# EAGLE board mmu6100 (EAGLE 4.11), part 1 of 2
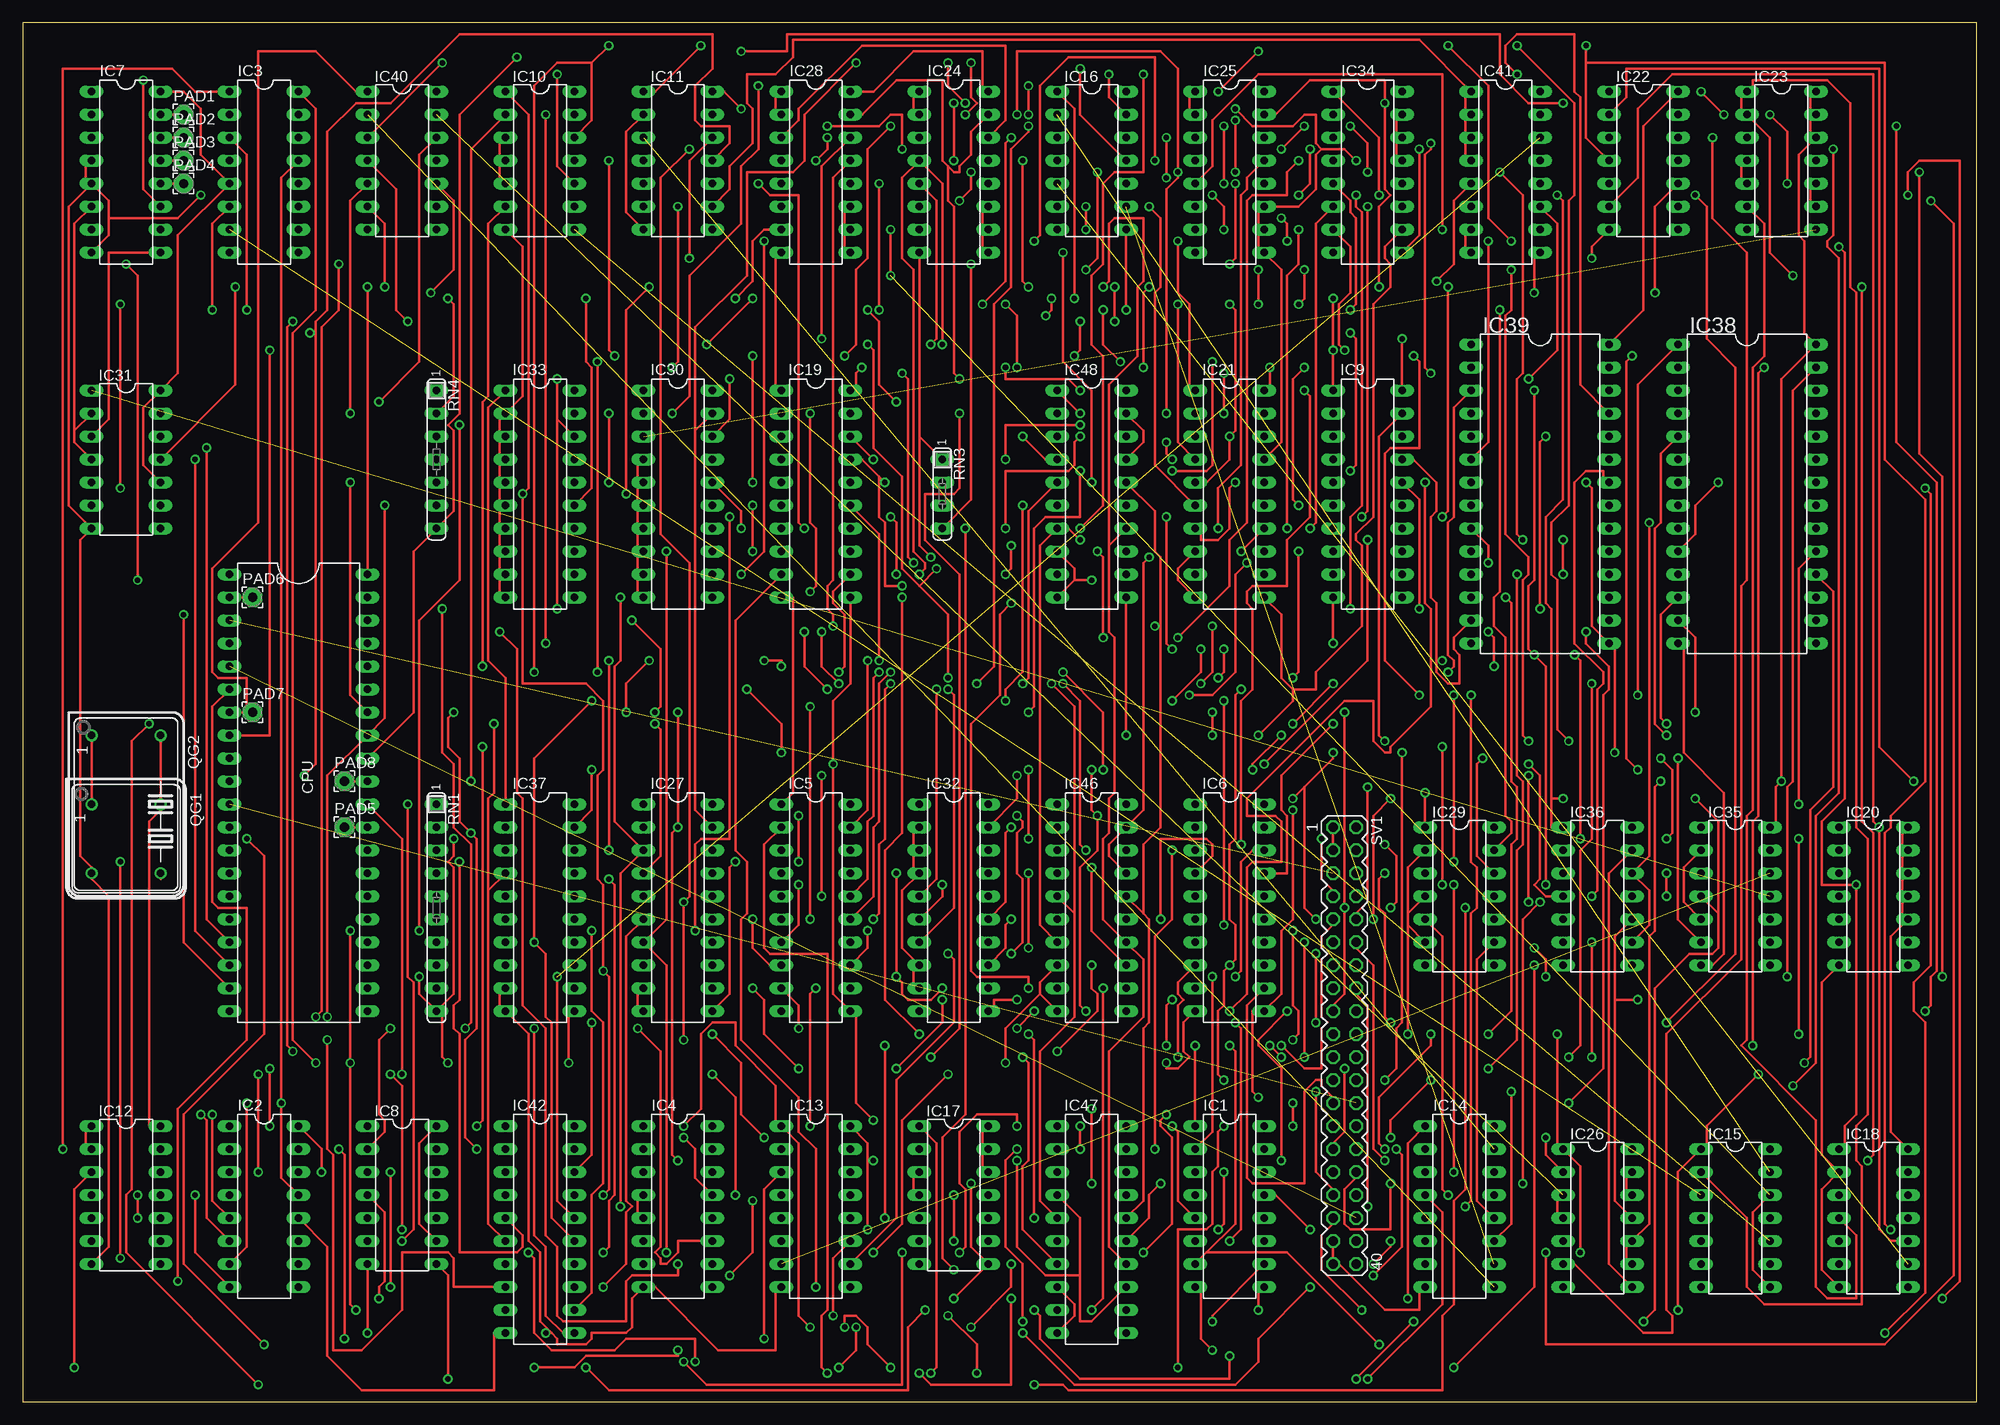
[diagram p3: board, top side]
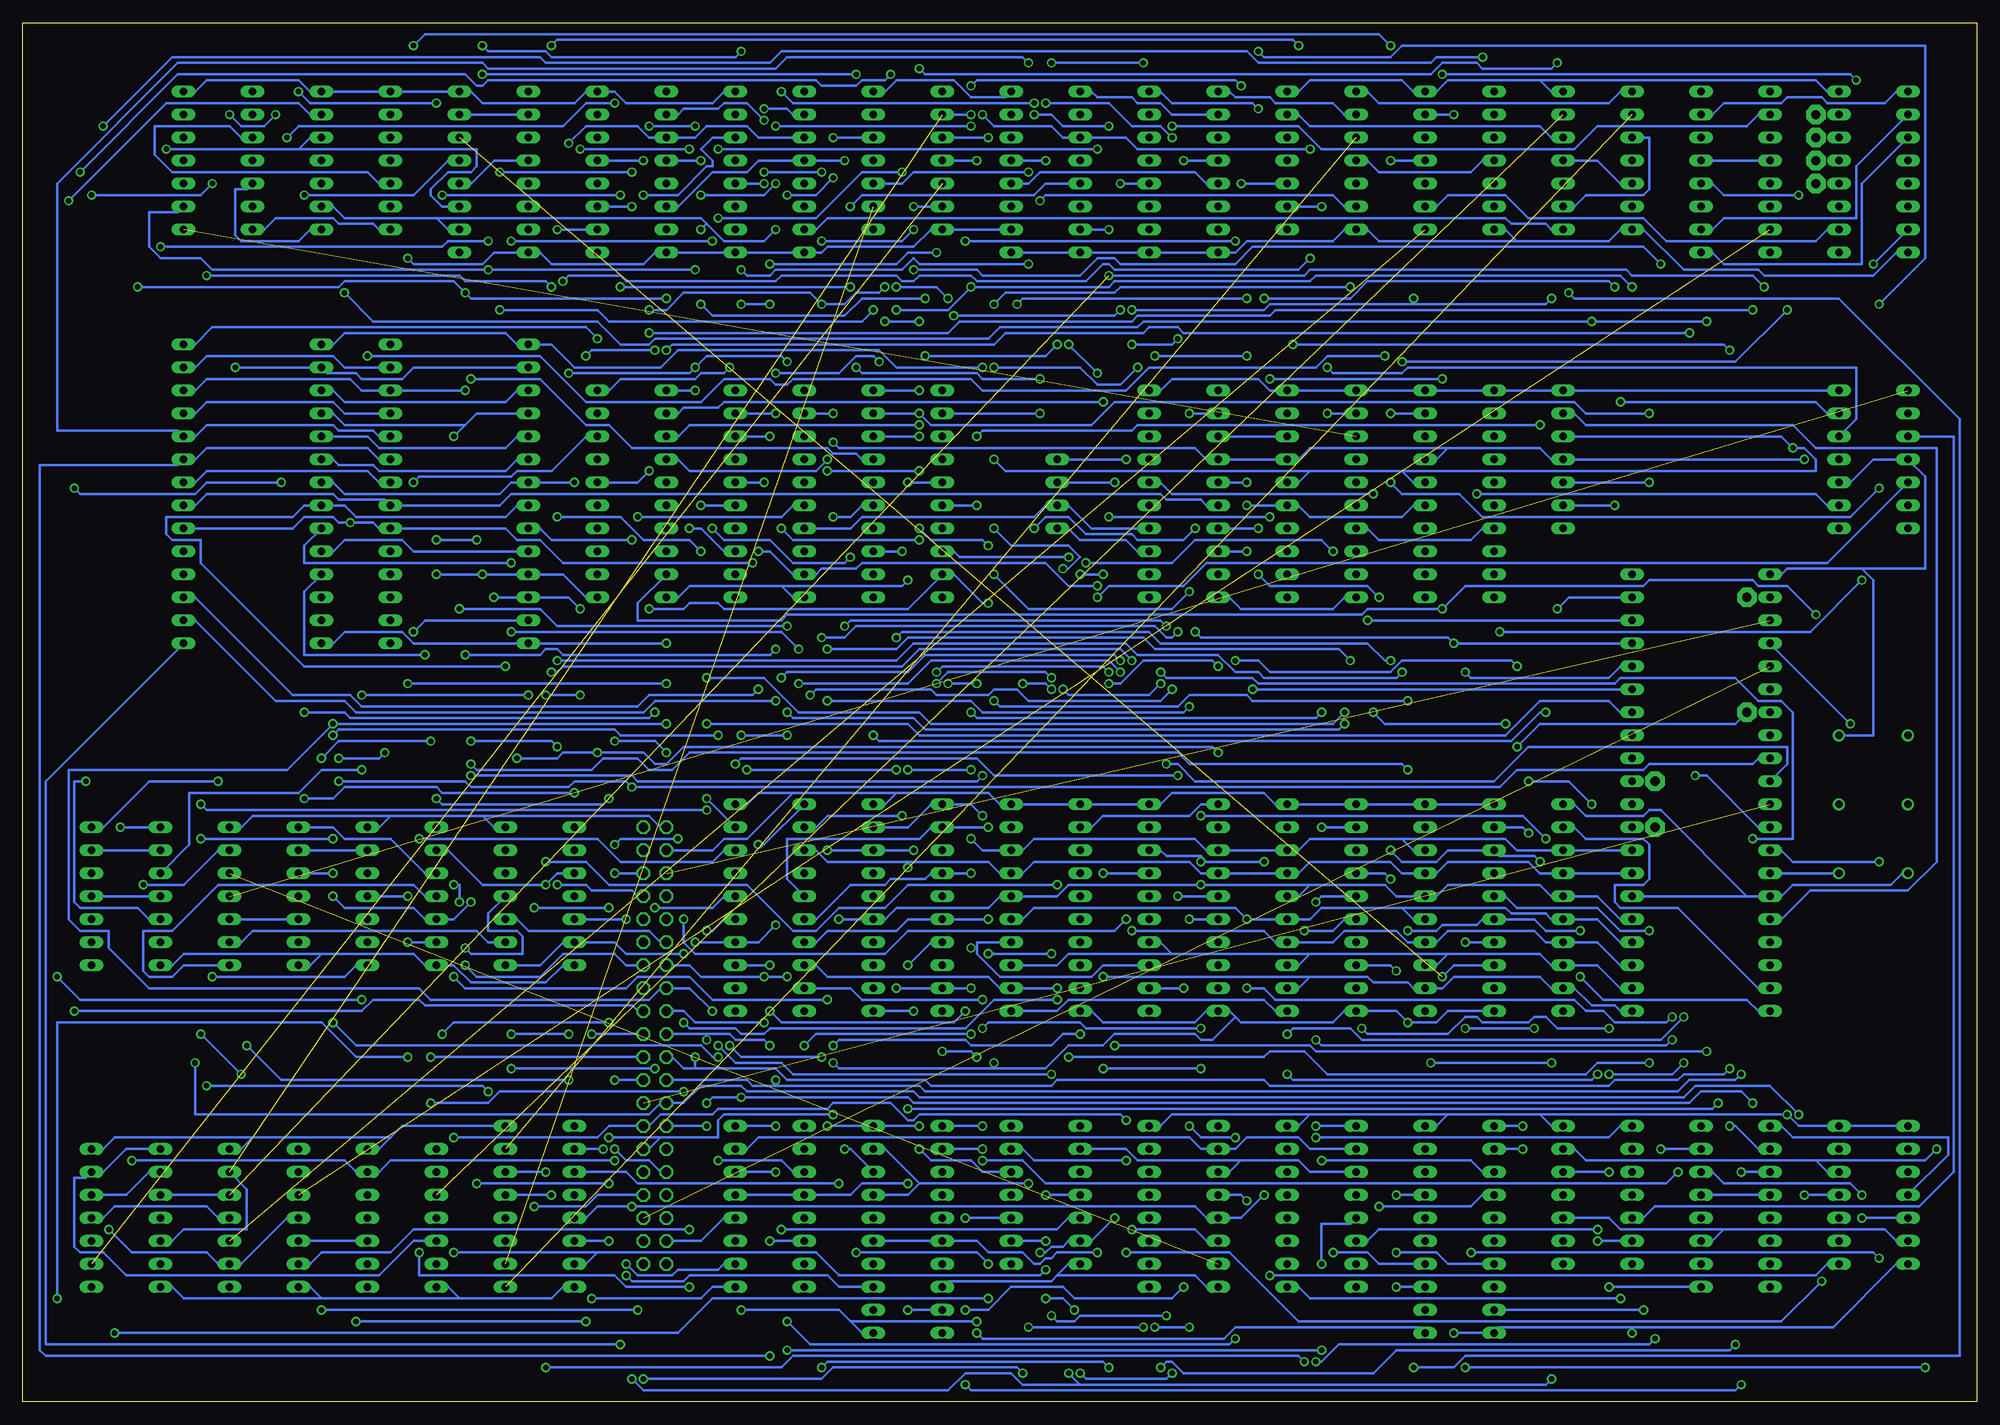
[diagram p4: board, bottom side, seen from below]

Size 215.9 x 152.4 mm. Coordinates in mm from the lower left corner, seen from the top.
Outline: 0,0 215.9,0 215.9,152.4 0,152.4 0,0
Copper layers (1*16): Top 0.035mm / dielectric 1.5mm / Bottom 0.035mm
Design rules "10mils": minimum track width 10mil, minimum drill 24mil, track to track 10mil, track to pad 10mil, pad to pad 10mil, via to via 10mil, smd to smd 10mil, copper to edge 40mil, drill to drill 10mil, minimum pad ring 10mil, minimum via ring 8mil, stop-mask expansion 0mil, vias tented up to drill 0mil, thermal gap 10mil

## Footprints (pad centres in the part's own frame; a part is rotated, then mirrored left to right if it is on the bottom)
DIL40 = drill 0.813 long: 1 -24.13,-7.62; 2 -21.59,-7.62; 3 -19.05,-7.62; 4 -16.51,-7.62; 5 -13.97,-7.62; 6 -11.43,-7.62; 7 -8.89,-7.62; 8 -6.35,-7.62; 9 -3.81,-7.62; 10 -1.27,-7.62; 11 1.27,-7.62; 12 3.81,-7.62; 13 6.35,-7.62; 14 8.89,-7.62; 15 11.43,-7.62; 16 13.97,-7.62; 17 16.51,-7.62; 18 19.05,-7.62; 19 21.59,-7.62; 20 24.13,-7.62; 21 24.13,7.62; 22 21.59,7.62; 23 19.05,7.62; 24 16.51,7.62; 25 13.97,7.62; 26 11.43,7.62; 27 8.89,7.62; 28 6.35,7.62; 29 3.81,7.62; 30 1.27,7.62; 31 -1.27,7.62; 32 -3.81,7.62; 33 -6.35,7.62; 34 -8.89,7.62; 35 -11.43,7.62; 36 -13.97,7.62; 37 -16.51,7.62; 38 -19.05,7.62; 39 -21.59,7.62; 40 -24.13,7.62
DIL16 = drill 0.813 long: 1 -8.89,-3.81; 2 -6.35,-3.81; 3 -3.81,-3.81; 4 -1.27,-3.81; 5 1.27,-3.81; 6 3.81,-3.81; 7 6.35,-3.81; 8 8.89,-3.81; 9 8.89,3.81; 10 6.35,3.81; 11 3.81,3.81; 12 1.27,3.81; 13 -1.27,3.81; 14 -3.81,3.81; 15 -6.35,3.81; 16 -8.89,3.81
DIL20 = drill 0.813 long: 1 -11.43,-3.81; 2 -8.89,-3.81; 3 -6.35,-3.81; 4 -3.81,-3.81; 5 -1.27,-3.81; 6 1.27,-3.81; 7 3.81,-3.81; 8 6.35,-3.81; 9 8.89,-3.81; 10 11.43,-3.81; 11 11.43,3.81; 12 8.89,3.81; 13 6.35,3.81; 14 3.81,3.81; 15 1.27,3.81; 16 -1.27,3.81; 17 -3.81,3.81; 18 -6.35,3.81; 19 -8.89,3.81; 20 -11.43,3.81
DIL14 = drill 0.813 long: 1 -7.62,-3.81; 2 -5.08,-3.81; 3 -2.54,-3.81; 4 0,-3.81; 5 2.54,-3.81; 6 5.08,-3.81; 7 7.62,-3.81; 8 7.62,3.81; 9 5.08,3.81; 10 2.54,3.81; 11 0,3.81; 12 -2.54,3.81; 13 -5.08,3.81; 14 -7.62,3.81
DIL28-6 = drill 0.813 long: 1 -16.51,-7.62; 2 -13.97,-7.62; 3 -11.43,-7.62; 4 -8.89,-7.62; 5 -6.35,-7.62; 6 -3.81,-7.62; 7 -1.27,-7.62; 8 1.27,-7.62; 9 3.81,-7.62; 10 6.35,-7.62; 11 8.89,-7.62; 12 11.43,-7.62; 13 13.97,-7.62; 14 16.51,-7.62; 15 16.51,7.62; 16 13.97,7.62; 17 11.43,7.62; 18 8.89,7.62; 19 6.35,7.62; 20 3.81,7.62; 21 1.27,7.62; 22 -1.27,7.62; 23 -3.81,7.62; 24 -6.35,7.62; 25 -8.89,7.62; 26 -11.43,7.62; 27 -13.97,7.62; 28 -16.51,7.62
2,15/1,0 = drill 1.016 pad 2.159 octagon: 1 0,0
DIL08S = drill 0.813 round: 1 -3.81,-3.81; 4 3.81,-3.81; 5 3.81,3.81; 8 -3.81,3.81
DIL14S = drill 0.813 round: 1 -7.62,-3.81; 7 7.62,-3.81; 8 7.62,3.81; 14 -7.62,3.81
SIL10 = drill 0.813 long: 1 -11.43,0; 2 -8.89,0; 3 -6.35,0; 4 -3.81,0; 5 -1.27,0; 6 1.27,0; 7 3.81,0; 8 6.35,0; 9 8.89,0; 10 11.43,0
SIL4 = drill 0.813 long: 1 -3.81,0; 2 -1.27,0; 3 1.27,0; 4 3.81,0
SIL7 = drill 0.813 long: 1 -7.62,0; 2 -5.08,0; 3 -2.54,0; 4 0,0; 5 2.54,0; 6 5.08,0; 7 7.62,0
MA20-2 = drill 1.016 octagon: 1 -24.13,-1.27; 2 -24.13,1.27; 3 -21.59,-1.27; 4 -21.59,1.27; 5 -19.05,-1.27; 6 -19.05,1.27; 7 -16.51,-1.27; 8 -16.51,1.27; 9 -13.97,-1.27; 10 -13.97,1.27; 11 -11.43,-1.27; 12 -11.43,1.27; 13 -8.89,-1.27; 14 -8.89,1.27; 15 -6.35,-1.27; 16 -6.35,1.27; 17 -3.81,-1.27; 18 -3.81,1.27; 19 -1.27,-1.27; 20 -1.27,1.27; 21 1.27,-1.27; 22 1.27,1.27; 23 3.81,-1.27; 24 3.81,1.27; 25 6.35,-1.27; 26 6.35,1.27; 27 8.89,-1.27; 28 8.89,1.27; 29 11.43,-1.27; 30 11.43,1.27; 31 13.97,-1.27; 32 13.97,1.27; 33 16.51,-1.27; 34 16.51,1.27; 35 19.05,-1.27; 36 19.05,1.27; 37 21.59,-1.27; 38 21.59,1.27; 39 24.13,-1.27; 40 24.13,1.27

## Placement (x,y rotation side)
CPU  IM6100  [DIL40]  30.48,67.31 270 top
IC1  74LS75N  [DIL16]  133.35,21.59 270 top
IC2  74LS75N  [DIL16]  26.67,21.59 270 top
IC3  74LS75N  [DIL16]  26.67,135.89 270 top
IC4  74HCT138N  [DIL16]  72.39,21.59 270 top
IC5  74LS373N  [DIL20]  87.63,54.61 270 top
IC6  74LS245N  [DIL20]  133.35,54.61 270 top
IC7  74HCT138N  [DIL16]  11.43,135.89 270 top
IC8  [DIL14]  41.91,22.86 270 top
IC9  74LS245N  [DIL20]  148.59,100.33 270 top
IC10  74HCT00N  [DIL14]  57.15,137.16 270 top
IC11  74LS74N  [DIL14]  72.39,137.16 270 top
IC12  74LS30N  [DIL14]  11.43,22.86 270 top
IC13  74HCT138N  [DIL16]  87.63,21.59 270 top
IC14  74HCT138N  [DIL16]  158.75,21.59 270 top
IC15  74HCT08N  [DIL14]  189.23,20.32 270 top
IC16  74LS32N  [DIL14]  118.11,137.16 270 top
IC17  74LS32N  [DIL14]  102.87,22.86 270 top
IC18  74LS74N  [DIL14]  204.47,20.32 270 top
IC19  74LS373N  [DIL20]  87.63,100.33 270 top
IC20  74LS74N  [DIL14]  204.47,55.88 270 top
IC21  74LS241N  [DIL20]  133.35,100.33 270 top
IC22  [DIL14]  179.07,137.16 270 top
IC23  74HCT00N  [DIL14]  194.31,137.16 270 top
IC24  74LS173N  [DIL16]  102.87,135.89 270 top
IC25  74LS173N  [DIL16]  133.35,135.89 270 top
IC26  74HCT00N  [DIL14]  173.99,20.32 270 top
IC27  74LS245N  [DIL20]  72.39,54.61 270 top
IC28  74LS173N  [DIL16]  87.63,135.89 270 top
IC29  74LS07N  [DIL14]  158.75,55.88 270 top
IC30  74LS245N  [DIL20]  72.39,100.33 270 top
IC31  74LS74N  [DIL14]  11.43,104.14 270 top
IC32  74LS245N  [DIL20]  102.87,54.61 270 top
IC33  74LS245N  [DIL20]  57.15,100.33 270 top
IC34  74LS157N  [DIL16]  148.59,135.89 270 top
IC35  74LS32N  [DIL14]  189.23,55.88 270 top
IC36  74HCT08N  [DIL14]  173.99,55.88 270 top
IC37  74LS245N  [DIL20]  57.15,54.61 270 top
IC38  [DIL28-6]  190.5,100.33 270 top
IC39  [DIL28-6]  167.64,100.33 270 top
IC40  74LS11N  [DIL14]  41.91,137.16 270 top
IC41  74LS151N  [DIL16]  163.83,135.89 270 top
IC42  74LS273N  [DIL20]  57.15,19.05 270 top
IC46  74LS244N  [DIL20]  118.11,54.61 270 top
IC47  74LS244N  [DIL20]  118.11,19.05 270 top
IC48  74LS244N  [DIL20]  118.11,100.33 270 top
PAD1  [2,15/1,0]  17.78,142.24 0 top
PAD2  [2,15/1,0]  17.78,139.7 0 top
PAD3  [2,15/1,0]  17.78,137.16 0 top
PAD4  [2,15/1,0]  17.78,134.62 0 top
PAD5  [2,15/1,0]  35.56,63.5 0 top
PAD6  [2,15/1,0]  25.4,88.9 0 top
PAD7  [2,15/1,0]  25.4,76.2 0 top
PAD8  [2,15/1,0]  35.56,68.58 0 top
QG1  [DIL08S]  11.43,62.23 270 top
QG2  [DIL14S]  11.43,66.04 270 top
RN1  100K  [SIL10]  45.72,54.61 270 top
RN3  100K  [SIL4]  101.6,100.33 270 top
RN4  [SIL7]  45.72,104.14 270 top
SV1  [MA20-2]  146.05,39.37 270 top

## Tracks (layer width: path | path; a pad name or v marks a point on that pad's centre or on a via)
00\  (via drill 0.61)
  Top 0.254: v78.11,13.97 80.64,16.51 v80.64,22.23
  Bottom 0.254: v78.11,13.97 17.78,13.97 16.51,15.24 IC12.8 | v80.64,22.23 81.28,22.86 IC13.4
2X\  (via drill 0.61)
  Top 0.254: v46.99,2.54 46.99,13.97 IC8.8 | v100.33,3.17 100.97,3.81 100.97,28.57 IC17.1 | v148.59,2.54 156.84,10.79 156.84,20.95 IC14.4
  Bottom 0.254: v46.99,2.54 47.62,1.91 99.06,1.91 | 99.06,1.91 v100.33,3.17 | v148.59,2.54 147.32,1.27 113.67,1.27 111.76,3.17 106.68,3.17 105.41,1.91 99.06,1.91
AND\
  Top 0.254: IC7.15 PAD1.1
BFLD0
  Bottom 0.254: IC28.5 85.09,134.62 86.36,135.89 103.5,135.89 104.78,134.62 IC24.12
BFLD1  (via drill 0.61)
  Top 0.254: v87.63,137.16 88.9,138.43 v88.9,139.7 | v102.87,143.51 v102.87,137.16
  Bottom 0.254: v88.9,139.7 90.17,140.97 93.34,140.97 95.89,143.51 v102.87,143.51 | IC28.4 v87.63,137.16 | v102.87,137.16 IC24.13
BFLD2
  Top 0.254: IC28.3 85.72,141.6 85.72,142.88 92.71,149.86 108.58,149.86 108.58,141.6 IC24.14
BFLOAD  (via drill 0.61)
  Top 0.254: v40.01,123.19 40.01,130.18 IC40.6 | v78.74,121.92 80.64,123.83 80.64,128.27 81.92,129.54 IC28.7
  Bottom 0.254: v40.01,123.19 40.64,123.83 67.31,123.83 69.22,121.92 v78.74,121.92
BMUX0  (via drill 0.61)
  Top 0.254: IC47.14 120.02,17.14 120.02,38.73 123.83,42.55 123.83,48.9 IC46.14 119.38,53.34 119.38,62.23 120.02,62.87 120.02,66.67 120.65,67.31 120.65,84.45 120.02,85.09 120.02,94.61 | 120.02,94.61 IC48.14 | v94.61,120.65 v94.61,134.62 | v113.03,120.02 113.67,120.65 v113.67,121.92 | v119.38,123.19 120.02,123.83 120.02,130.18 120.65,130.81 123.83,130.81 123.83,123.83 123.19,123.19 123.19,115.57 120.02,112.39 120.02,94.61
  Bottom 0.254: v94.61,120.65 95.25,120.02 v113.03,120.02 | v113.67,121.92 114.94,123.19 v119.38,123.19 | v94.61,134.62 IC28.12
BMUX1  (via drill 0.61)
  Top 0.254: 123.83,53.98 124.46,53.34 124.46,41.91 123.83,41.27 123.83,22.23 IC47.16 | 123.83,53.98 IC46.16 | 125.73,85.72 125.73,63.5 123.83,61.59 123.83,53.98 | 125.73,85.72 125.73,93.34 125.09,93.98 125.09,98.42 IC48.16 | v89.53,85.72 89.53,87 88.9,87.63 88.9,90.17 89.53,90.81 89.53,135.25 IC28.13 | 125.73,85.72 v125.09,85.72
  Bottom 0.254: v89.53,85.72 90.17,86.36 124.46,86.36 v125.09,85.72
BMUX2  (via drill 0.61)
  Top 0.254: v88.27,117.47 88.27,136.53 IC28.14 | v93.34,116.84 93.98,116.2 93.98,105.41 97.16,102.23 97.16,92.08 99.06,90.17 | 99.06,90.17 102.23,87 v102.23,80.01 | v114.94,79.38 116.84,77.47 116.84,61.59 v117.47,60.96 | v125.09,27.94 125.09,51.44 127,53.34 v127,60.96 | v116.84,106.68 116.2,106.05 116.2,103.5 115.57,102.87 108.58,102.87 v108.58,96.52 | 99.06,90.17 v100.97,92.08
  Bottom 0.254: v88.27,117.47 88.9,116.84 v93.34,116.84 | v102.23,80.01 102.87,80.64 113.67,80.64 v114.94,79.38 | v117.47,60.96 IC46.18 v127,60.96 | v125.09,27.94 124.46,27.94 IC47.18 | v108.58,96.52 106.68,94.61 100.33,94.61 99.06,93.34 100.33,92.08 v100.97,92.08 | v116.84,106.68 IC48.18
C0\  (via drill 0.61)
  Top 0.254: CPU.32 43.18,76.2 43.18,93.98 RN4.7 47.62,98.42 47.62,107.31 46.99,107.95 48.26,109.22 48.26,142.24 v54.61,148.59 | v210.19,43.18 210.82,43.81 210.82,46.99 211.46,47.62 211.46,101.6 207.01,106.05 v207.01,140.97
  Bottom 0.254: v210.19,43.18 178.44,43.18 177.16,44.45 172.09,44.45 171.45,43.81 148.59,43.81 147.96,43.18 SV1.18 | v207.01,140.97 199.39,148.59 158.75,148.59 158.12,147.96 133.35,147.96 132.08,149.22 80.64,149.22 79.38,147.96 60.33,147.96 59.69,148.59 v54.61,148.59
C1\  (via drill 0.61)
  Top 0.254: v40.01,99.06 40.01,75.56 CPU.33 33.66,69.22 v33.66,42.55 | 153.03,52.7 153.03,53.98 | 153.03,53.98 IC29.4 | IC29.6 153.03,52.7 | 153.03,53.98 153.03,59.05 IC29.2 | 153.03,52.7 v153.03,40.64 | v80.64,45.72 81.92,44.45 81.92,40.64 v85.72,36.83 | v96.52,36.83 101.6,41.91 v101.6,44.45 | v142.88,41.91 v142.88,49.53
  Bottom 0.254: v40.01,99.06 RN4.6 | IC29.8 158.75,48.26 156.21,50.8 IC29.6 150.5,50.8 149.22,49.53 v142.88,49.53 | v153.03,40.64 SV1.20 | v33.66,42.55 34.29,41.91 40.01,41.91 41.27,43.18 43.18,43.18 44.45,44.45 77.47,44.45 78.74,45.72 v80.64,45.72 | v85.72,36.83 v96.52,36.83 | v101.6,44.45 108.58,44.45 111.76,41.27 133.35,41.27 133.99,40.64 136.53,40.64 137.16,41.27 142.24,41.27 v142.88,41.91
C2\  (via drill 0.61)
  Top 0.254: v36.2,101.6 36.2,78.11 CPU.34 | v170.81,38.1 172.09,39.37 172.09,60.96 173.35,62.23 v173.35,79.38 | v140.34,74.93 v144.78,79.38
  Bottom 0.254: v36.2,101.6 RN4.5 | v144.78,79.38 v173.35,79.38 | v140.34,74.93 118.11,74.93 116.84,73.66 52.07,73.66 48.26,77.47 40.64,77.47 39.37,76.2 CPU.34 | v170.81,38.1 SV1.22
CAF\  (1 unrouted)
CDF\  (via drill 0.61)
  Top 0.254: v104.78,24.13 104.78,17.14 IC17.8 v102.87,11.43 | v45.09,122.56 47.62,125.09 47.62,132.72 IC40.10 | v62.23,3.81 64.77,1.27 97.79,1.27 97.79,8.26 v99.69,10.16
  Bottom 0.254: v104.78,24.13 116.84,24.13 | 116.84,24.13 118.11,22.86 IC47.17 | 116.84,24.13 120.65,27.94 IC47.19 | v45.09,122.56 44.45,121.92 15.24,121.92 1.91,108.58 1.91,5.08 56.52,5.08 57.78,3.81 v62.23,3.81 | v99.69,10.16 100.97,11.43 v102.87,11.43
CIF\  (via drill 0.61)
  Top 0.254: v103.5,16.51 104.14,17.14 104.14,23.5 103.5,24.13 103.5,29.84 105.41,31.75 109.86,31.75 v109.86,30.48 | v180.34,122.56 180.34,132.08 IC22.10 | v42.55,119.38 41.27,120.65 41.27,133.99 IC40.4 | v95.25,39.37 v95.25,20.32 | v29.84,38.73 29.21,39.37 29.21,118.75 v29.84,119.38
  Bottom 0.254: v103.5,16.51 102.87,16.51 102.23,17.14 100.97,17.14 100.33,17.78 IC17.6 97.79,17.78 v95.25,20.32 | v109.86,30.48 IC47.1 | v180.34,122.56 177.16,119.38 152.4,119.38 149.86,116.84 146.69,116.84 146.05,117.47 109.22,117.47 107.95,118.75 92.71,118.75 92.08,119.38 v42.55,119.38 v29.84,119.38 | v95.25,39.37 73.66,39.37 73.03,38.73 v29.84,38.73
CINT\  (1 unrouted)
CPREQ\  (1 unrouted)
CPSEL
  Bottom 0.254: IC22.5 176.53,134.62 177.8,135.89 199.39,135.89 201.29,137.79 201.29,140.97 193.04,140.97 191.77,139.7 IC23.3
CPSEL\  (via drill 0.61)
  Top 0.254: IC15.2 190.5,20.32 190.5,12.7 192.41,10.79 203.2,10.79 203.2,26.04 202.56,26.67 202.56,30.48 203.84,31.75 203.84,62.23 202.56,63.5 202.56,122.56 201.93,123.19 201.93,143.51 199.39,146.05 191.13,146.05 191.13,145.41 IC23.1 189.87,144.15 189.87,142.88 IC23.2 193.04,139.7 193.04,127 v195.58,124.46 | v67.31,86.36 70.48,83.19 70.48,76.83 v69.85,76.2 | v140.34,80.01 140.97,80.64 v140.97,93.98 | v156.84,97.79 157.48,98.42 v157.48,123.19
  Bottom 0.254: v69.85,76.2 71.12,74.93 115.57,74.93 116.84,76.2 130.18,76.2 133.99,80.01 v140.34,80.01 | v140.97,93.98 142.24,95.25 147.32,95.25 149.86,97.79 v156.84,97.79 | v157.48,123.19 158.12,123.83 167,123.83 167.64,124.46 v195.58,124.46 | v67.31,86.36 CPU.38
CPUDX0  (via drill 0.61)
  Top 0.254: v80.64,99.06 v80.64,93.98 | v96.52,110.49 94.61,112.39 94.61,119.38 v93.34,120.65 | v46.99,121.92 47.62,121.28 47.62,111.12 RN4.2 | v62.23,121.92 62.23,114.94 62.87,114.3 62.87,100.97 IC33.15
  Bottom 0.254: IC33.15 62.23,99.06 63.5,97.79 73.66,97.79 74.93,99.06 IC30.15 v80.64,99.06 | v80.64,93.98 IC19.8 | CPU.16 21.59,53.34 18.41,56.52 7.62,56.52 4.45,59.69 4.45,105.41 17.78,105.41 20.32,107.95 43.18,107.95 44.45,109.22 RN4.2 | v96.52,110.49 138.43,110.49 139.06,109.86 142.88,109.86 143.51,109.22 IC9.2 | v93.34,120.65 78.74,120.65 78.11,121.28 62.23,121.28 | 62.23,121.28 47.62,121.28 v46.99,121.92 | 62.23,121.28 v62.23,121.92
CPUDX1  (via drill 0.61)
  Top 0.254: v20.32,105.41 20.32,53.34 CPU.17 | v79.38,96.52 79.38,98.42 IC30.16 | v116.84,107.95 108.58,107.95 v108.58,104.14
  Bottom 0.254: RN4.3 21.59,106.68 v20.32,105.41 19.05,105.41 17.78,104.14 17.78,102.87 63.5,102.87 | 63.5,102.87 62.23,101.6 IC33.16 | 63.5,102.87 73.66,102.87 | 73.66,102.87 74.93,101.6 IC30.16 | v79.38,96.52 IC19.7 | v116.84,107.95 142.24,107.95 143.51,106.68 IC9.3 | v108.58,104.14 107.31,102.87 73.66,102.87
CPUDX2  (via drill 0.61)
  Top 0.254: v127,104.14 126.36,104.78 v126.36,106.05 | v19.05,104.14 19.05,52.07 CPU.18
  Bottom 0.254: v127,104.14 128.27,102.87 142.24,102.87 143.51,104.14 IC9.4 | v126.36,106.05 125.73,105.41 86.36,105.41 85.09,104.14 IC19.4 IC30.17 74.93,104.14 73.66,105.41 58.42,105.41 | v19.05,104.14 RN4.4 46.99,104.14 48.26,105.41 58.42,105.41 | 58.42,105.41 59.69,104.14 IC33.17
CPUDX3  (via drill 0.61)
  Top 0.254: 59.05,108.58 v59.05,113.03 | v78.11,113.03 78.11,108.58 IC30.18 | 59.05,108.58 IC33.18 | v59.05,87.63 59.05,108.58 | v17.78,87 17.78,50.8 CPU.19
  Bottom 0.254: CPU.19 24.13,45.72 33.02,54.61 39.37,54.61 40.01,55.24 40.01,57.15 36.83,57.15 36.2,57.78 36.2,61.59 36.83,62.23 43.18,62.23 44.45,63.5 RN1.2 | v59.05,113.03 v78.11,113.03 | IC30.18 IC19.3 | IC9.9 147.96,88.27 147.96,86.36 132.08,86.36 131.44,87 67.94,87 67.31,87.63 v59.05,87.63 56.52,90.17 36.83,90.17 36.2,90.81 24.77,90.81 24.13,90.17 20.95,90.17 v17.78,87
CPUDX4  (via drill 0.61)
  Top 0.254: v43.81,46.99 43.81,45.09 RN1.10 | v60.33,37.47 60.33,42.55 IC37.11 | v46.99,37.47 46.35,38.1 46.35,42.55 RN1.10 | v109.86,44.45 107.31,44.45 107.31,43.81 IC32.11 | v78.74,59.69 78.11,59.05 78.11,45.09 IC27.11 | v47.62,62.23 47.62,60.33 46.99,59.69 47.62,59.05 47.62,45.09 RN1.10 | v85.72,64.77 v85.72,59.69
  Bottom 0.254: v43.81,46.99 41.27,44.45 25.4,44.45 24.13,43.18 CPU.20 | v46.99,37.47 v60.33,37.47 | IC27.11 77.47,43.18 78.74,44.45 100.33,44.45 101.6,43.18 IC32.11 | v109.86,44.45 123.19,44.45 124.46,45.72 IC6.9 | 85.09,59.69 85.72,60.33 89.53,60.33 90.17,60.96 IC5.18 | 85.09,59.69 v78.74,59.69 | v47.62,62.23 50.16,64.77 v85.72,64.77 | v85.72,59.69 85.09,59.69
CPUDX5  (via drill 0.61)
  Top 0.254: v96.52,58.42 v96.52,46.99 97.16,46.35 97.16,45.09 97.79,44.45 100.33,44.45 v101.6,45.72 | v184.78,133.35 186.06,132.08 186.06,117.47 189.23,114.3 189.23,49.53 v181.61,41.91 | v139.06,38.1 v137.79,39.37 | v127.64,38.1 127.64,43.81 128.27,44.45 127.64,45.09 127.64,46.35 IC6.8
  Bottom 0.254: CPU.21 39.37,43.18 40.01,43.81 42.55,43.81 44.45,45.72 RN1.9 46.99,45.72 48.26,46.99 57.78,46.99 59.05,45.72 IC37.12 62.23,45.72 62.87,46.35 66.67,46.35 67.31,46.99 73.66,46.99 | 73.66,46.99 74.93,45.72 IC27.12 | v96.52,46.99 73.66,46.99 | v96.52,58.42 IC5.17 | IC6.8 128.27,48.26 127,46.99 109.22,46.99 107.95,45.72 IC32.12 v101.6,45.72 | v184.78,133.35 172.72,133.35 168.91,137.16 IC41.13 | v181.61,41.91 179.07,39.37 140.97,39.37 139.7,38.1 v139.06,38.1 | v137.79,39.37 136.53,38.1 v127.64,38.1
CPUDX6  (via drill 0.61)
  Top 0.254: v109.22,53.34 108.58,52.7 108.58,50.16 IC32.13
  Bottom 0.254: IC6.7 128.27,50.8 127,52.07 119.38,52.07 118.11,53.34 IC46.6 v109.22,53.34 | CPU.22 39.37,45.72 41.91,48.26 RN1.8 46.99,48.26 48.26,49.53 58.42,49.53 | 58.42,49.53 59.69,48.26 IC37.13 | 73.66,49.53 74.93,48.26 IC27.13 | 58.42,49.53 73.66,49.53 | 88.9,49.53 90.17,50.8 IC5.14 | 73.66,49.53 88.9,49.53 | 88.9,49.53 100.33,49.53 101.6,48.26 IC32.13
CPUDX7  (via drill 0.61)
  Top 0.254: v93.34,52.07 93.34,50.16 IC5.13 | v111.12,50.16 v111.12,58.42
  Bottom 0.254: IC6.6 128.27,53.34 124.46,57.15 120.65,57.15 120.02,57.78 116.2,57.78 115.57,58.42 IC46.4 v111.12,58.42 | 110.49,50.16 110.49,50.8 IC32.14 | 110.49,50.16 110.49,49.53 107.95,46.99 97.79,46.99 96.52,48.26 IC5.13 | CPU.23 39.37,48.26 41.91,50.8 RN1.7 47.62,50.8 48.9,52.07 58.42,52.07 59.69,50.8 IC37.14 62.87,50.8 64.14,52.07 69.85,52.07 71.12,50.8 IC27.14 77.47,50.8 78.74,52.07 v93.34,52.07 | 110.49,50.16 v111.12,50.16
CPUDX8  (via drill 0.61)
  Top 0.254: v80.64,53.34 80.64,50.16 82.55,48.26 IC5.8 | v109.22,63.5 108.58,62.87 108.58,55.24 IC32.15
  Bottom 0.254: IC6.5 131.44,57.78 131.44,62.23 116.84,62.23 115.57,63.5 IC46.2 v109.22,63.5 | CPU.24 39.37,50.8 41.91,53.34 RN1.6 46.99,53.34 47.62,53.98 51.44,53.98 52.07,54.61 63.5,54.61 | 63.5,54.61 62.23,53.34 IC37.15 | 63.5,54.61 72.39,54.61 73.66,53.34 IC27.15 v80.64,53.34 81.92,54.61 104.14,54.61 105.41,53.34 IC32.15
CPUDX9  (via drill 0.61)
  Top 0.254: v125.73,53.34 125.73,62.23 130.81,62.23 131.44,61.59 131.44,60.33 IC6.4 | v85.72,57.15 85.72,52.7 IC5.7
  Bottom 0.254: v125.73,53.34 IC46.15 120.65,53.34 119.38,54.61 109.22,54.61 107.95,55.88 IC32.16 101.6,55.88 100.33,57.15 v85.72,57.15 73.66,57.15 | CPU.25 39.37,53.34 41.91,55.88 RN1.5 46.99,55.88 48.26,57.15 58.42,57.15 59.69,55.88 IC37.16 64.14,55.88 65.41,57.15 73.66,57.15 | 73.66,57.15 74.93,55.88 IC27.16
CPUDX10  (via drill 0.61)
  Top 0.254: v118.11,59.05 118.11,52.07 IC46.13
  Bottom 0.254: 118.11,59.69 127,59.69 128.27,60.96 IC6.3 | 118.11,59.69 109.22,59.69 107.95,58.42 IC32.17 105.41,58.42 104.14,59.69 87,59.69 85.72,58.42 IC5.4 IC27.17 74.93,58.42 73.66,59.69 64.77,59.69 63.5,58.42 IC37.17 59.69,58.42 58.42,59.69 49.53,59.69 48.26,58.42 RN1.4 CPU.27 | 118.11,59.69 v118.11,59.05
CPUDX11  (via drill 0.61)
  Top 0.254: v117.47,43.18 116.84,43.81 116.84,59.05 118.75,60.96 v118.75,64.77 118.11,65.41 v118.11,69.85 | v111.12,62.23 v111.12,69.85
  Bottom 0.254: v118.75,64.77 127,64.77 128.27,63.5 IC6.2 | v117.47,43.18 IC46.11 | CPU.28 RN1.3 50.8,60.96 52.07,62.23 63.5,62.23 | 63.5,62.23 62.23,60.96 IC37.18 | 63.5,62.23 73.66,62.23 74.93,60.96 IC27.18 IC5.3 85.09,60.96 86.36,62.23 104.14,62.23 105.41,60.96 IC32.18 109.86,60.96 v111.12,62.23 | v111.12,69.85 v118.11,69.85
CPUINTREQ\  (via drill 0.61)
  Top 0.254: v27.3,116.2 27.3,73.66 CPU.8 | v80.64,121.92 v75.56,116.84 | v106.05,121.28 108.58,123.83 108.58,139.06 v109.22,139.7
  Bottom 0.254: v27.3,116.2 27.94,116.84 v75.56,116.84 | v80.64,121.92 105.41,121.92 v106.05,121.28 | IC16.3 v109.22,139.7
CUF\  (1 unrouted)
DATAF  (via drill 0.61)
  Top 0.254: v111.12,123.19 110.49,123.83 v110.49,137.16 | CPU.40 v38.1,123.19 | v132.72,113.67 v132.72,109.22 | v121.28,114.94 119.38,116.84 v119.38,120.65
  Bottom 0.254: v38.1,123.19 39.37,124.46 73.03,124.46 73.66,123.83 95.25,123.83 95.89,123.19 v111.12,123.19 113.67,120.65 v119.38,120.65 | v110.49,137.16 IC16.4 | v132.72,113.67 125.73,113.67 123.83,115.57 121.92,115.57 v121.28,114.94 | v132.72,109.22 IC21.19
DCA\
  Top 0.254: IC7.12 PAD4.1
DEVINTREQ  (1 unrouted)
DEVINTREQ\  (via drill 0.61)
  Top 0.254: IC23.9 197.49,132.72 197.49,133.99 IC23.10 | v116.2,121.92 116.2,142.88 IC16.1 | v140.97,121.28 141.6,121.92 v141.6,125.09 | v156.84,72.39 v156.84,57.15 | v166.37,73.03 165.74,73.66 165.74,90.81 166.37,91.44 166.37,93.34 163.83,95.89 163.83,120.02 164.47,120.65 v164.47,125.09
  Bottom 0.254: v116.2,121.92 123.19,121.92 125.09,120.02 139.7,120.02 v140.97,121.28 | v141.6,125.09 v164.47,125.09 194.94,125.09 196.22,126.36 200.66,126.36 201.93,127.64 201.93,131.44 198.75,131.44 IC23.9 | v156.84,57.15 153.67,57.15 153.03,56.52 148.59,56.52 147.96,55.88 SV1.8 | v156.84,72.39 157.48,73.03 v166.37,73.03
DEVSEL\  (via drill 0.61)
  Top 0.254: v41.91,36.2 41.91,62.23 CPU.30 | v76.2,36.2 78.74,33.66 v78.74,22.86 | v148.59,21.59 148.59,43.81 147.32,45.09 SV1.16
  Bottom 0.254: IC14.5 153.67,20.32 152.4,21.59 v148.59,21.59 86.36,21.59 85.09,20.32 IC13.5 81.28,20.32 v78.74,22.86 | v41.91,36.2 42.55,35.56 75.56,35.56 v76.2,36.2
DFLD0  (via drill 0.61)
  Top 0.254: v64.14,16.51 64.77,17.14 64.77,22.23 65.41,22.86 65.41,57.15 v64.77,57.78 | 140.34,78.74 139.06,80.01 139.06,87 IC21.11 | 140.34,78.74 142.88,78.74 142.88,80.64 147.96,85.72 147.96,94.61 147.32,95.25 147.32,95.89 149.22,97.79 149.22,121.28 151.13,123.19 151.13,125.73 150.5,126.36 150.5,127.64 IC34.10 | v156.84,129.54 156.84,146.69 136.53,146.69 131.44,141.6 131.44,136.53 IC25.5 | v69.85,74.93 70.48,74.3 70.48,60.33 IC27.4 | v131.44,73.66 v131.44,76.2 | v136.53,73.66 140.34,77.47 140.34,78.74
  Bottom 0.254: v64.14,16.51 59.69,16.51 58.42,15.24 IC42.7 | v64.77,57.78 65.41,58.42 IC27.4 | v156.84,129.54 IC34.10 | v69.85,74.93 70.48,74.3 116.2,74.3 117.47,75.56 130.81,75.56 v131.44,76.2 | v136.53,73.66 v131.44,73.66
DFLD1  (via drill 0.61)
  Top 0.254: v66.04,21.59 66.04,58.42 IC27.3 65.41,64.14 65.41,81.28 66.04,81.92 v66.04,88.9 | v142.24,96.52 142.88,97.16 142.88,130.18 IC34.6 | v79.38,91.44 81.92,93.98 v81.92,128.27 | v111.76,128.27 112.39,128.91 112.39,145.41 115.57,148.59 125.09,148.59 v125.09,137.16
  Bottom 0.254: v66.04,21.59 55.88,21.59 54.61,22.86 IC42.4 | IC34.6 143.51,132.08 139.7,135.89 135.89,135.89 134.62,137.16 IC25.4 v125.09,137.16 | v142.24,96.52 140.97,96.52 138.43,93.98 IC21.13 | v66.04,88.9 67.31,90.17 78.11,90.17 v79.38,91.44 | v111.76,128.27 v81.92,128.27
DFLD2  (via drill 0.61)
  Top 0.254: v72.39,26.67 71.75,27.3 71.75,62.87 v72.39,63.5 v72.39,76.2 | v140.97,99.06 140.34,99.69 140.34,113.03 v141.6,114.3 | v155.57,113.67 154.94,114.3 154.94,137.79 155.57,138.43 v155.57,139.06 | v111.12,76.2 111.76,76.83 111.76,96.52 113.03,97.79 116.84,97.79 v116.84,102.87 | v127,102.87 130.81,102.87 131.44,103.5 v131.44,114.94
  Bottom 0.254: v72.39,26.67 55.88,26.67 54.61,25.4 IC42.3 | v72.39,63.5 IC27.2 | v155.57,113.67 142.24,113.67 v141.6,114.3 140.34,115.57 132.08,115.57 v131.44,114.94 | v155.57,139.06 153.67,140.97 147.96,140.97 146.69,139.7 IC34.3 141.6,139.7 140.34,140.97 135.89,140.97 134.62,139.7 IC25.3 | v140.97,99.06 IC21.15 | v72.39,76.2 73.03,75.56 110.49,75.56 v111.12,76.2 | v127,102.87 v116.84,102.87
DFLOAD
  Bottom 0.254: IC40.8 46.99,129.54 47.62,130.18 51.44,130.18 52.07,130.81 127,130.81 128.27,129.54 IC25.7
DMAGNT  (1 unrouted)
DMAREQ\  (via drill 0.61)
  Top 0.254: v13.97,74.93 12.06,73.03 12.06,23.5 11.43,22.86 11.43,16.51 v26.04,1.91 | v111.76,1.91 114.94,1.91 115.57,1.27 156.84,1.27 156.84,9.53 158.12,10.79 158.12,22.23 159.38,23.5 v159.38,54.61 | v151.13,54.61 151.76,55.24 151.76,60.33 v150.5,61.59 | v143.51,62.23 143.51,57.78 144.78,56.52 SV1.7
  Bottom 0.254: v26.04,1.91 26.67,1.27 111.12,1.27 v111.76,1.91 | v159.38,54.61 v151.13,54.61 | v150.5,61.59 149.86,62.23 v143.51,62.23 | v13.97,74.93 CPU.4
DMUX0  (via drill 0.61)
  Top 0.254: 116.2,53.98 116.2,42.55 112.39,38.73 112.39,22.23 IC47.5 | 116.2,53.98 IC46.5 | v110.49,79.38 111.12,80.01 111.12,98.42 IC48.5 | v113.67,79.38 116.2,76.83 116.2,53.98 | v133.99,134.62 133.99,126.36 v133.35,125.73 | v114.94,127 114.94,114.94 118.11,111.76 v118.11,101.6
  Bottom 0.254: v110.49,79.38 v113.67,79.38 | v133.35,125.73 119.38,125.73 118.11,127 v114.94,127 | v133.99,134.62 IC25.12 | v118.11,101.6 IC48.5
DMUX1  (via drill 0.61)
  Top 0.254: v110.49,38.1 111.12,37.47 111.12,26.67 110.49,26.04 110.49,19.05 IC47.7 | v114.3,38.73 118.75,43.18 118.75,45.09 118.11,45.72 v118.11,48.26 | IC46.7 112.39,52.7 112.39,94.61 IC48.7 115.57,96.52 v116.84,95.25 | v132.08,96.52 132.08,100.97 134.62,103.5 134.62,133.35 135.25,133.99 135.25,135.25 IC25.13
  Bottom 0.254: v110.49,38.1 111.12,38.73 v114.3,38.73 | v118.11,48.26 115.57,50.8 IC46.7 | v132.08,96.52 130.81,95.25 v116.84,95.25
DMUX2  (via drill 0.61)
  Top 0.254: v118.11,10.16 119.38,11.43 v119.38,45.72 | v109.22,88.27 107.95,87 107.95,78.11 104.78,74.93 104.78,47.62 105.41,46.99 111.12,46.99 v111.12,45.72 | v147.32,133.35 147.32,132.08 147.96,131.44 147.96,99.06 146.69,97.79 v146.69,87.63
  Bottom 0.254: v118.11,10.16 IC47.9 | v119.38,45.72 IC46.9 v111.12,45.72 | v109.22,88.27 109.86,88.27 113.03,91.44 IC48.9 118.11,87.63 138.43,87.63 139.06,88.27 142.24,88.27 142.88,87.63 v146.69,87.63 | v147.32,133.35 143.51,133.35 140.34,136.53 139.7,136.53 139.7,137.16 140.97,138.43 139.7,139.7 IC25.14
DORTF\  (via drill 0.61)
  Top 0.254: v116.84,147.32 116.84,142.24 IC16.11 | v46.35,147.96 IC40.3
  Bottom 0.254: IC40.9 44.45,132.08 43.18,133.35 36.83,133.35 36.2,133.99 36.2,139.7 IC40.3 | v116.84,147.32 116.2,146.69 60.33,146.69 59.05,147.96 55.24,147.96 54.61,147.32 46.99,147.32 v46.35,147.96
EMA0  (via drill 0.61)
  Top 0.254: v66.67,100.33 66.67,120.65 v69.22,123.19 | v108.58,121.28 109.86,120.02 v109.86,114.3 | v159.38,21.59 160.02,22.23 160.02,53.98 160.66,54.61 160.66,59.05 160.02,59.69 v160.02,78.11 | v178.44,78.11 178.44,112.39 IC38.1
  Bottom 0.254: v66.67,100.33 88.9,100.33 90.17,101.6 IC19.16 | v69.22,123.19 94.61,123.19 95.25,122.56 107.31,122.56 v108.58,121.28 | v109.86,114.3 119.38,114.3 121.28,116.2 143.51,116.2 145.41,114.3 154.94,114.3 157.48,116.84 IC39.1 161.29,116.84 162.56,118.11 180.34,118.11 181.61,116.84 IC38.1 | v159.38,21.59 153.67,21.59 152.4,22.86 SV1.34 | v178.44,78.11 v160.02,78.11
EMA1  (via drill 0.61)
  Top 0.254: v94.61,81.92 94.61,95.89 IC19.15 | v132.08,80.01 132.72,80.64 v132.72,83.19 | v167,111.76 167,90.81 166.37,90.17 166.37,83.19 v167,82.55 168.28,81.28 v168.28,57.15 | v151.13,24.13 151.13,19.05 146.69,19.05 146.05,19.68 146.05,23.5 147.32,24.77 SV1.32 | v165.74,24.13 165.74,53.34 v167.64,55.24
  Bottom 0.254: v94.61,81.92 95.25,82.55 116.2,82.55 118.11,80.64 131.44,80.64 v132.08,80.01 | v132.72,83.19 133.35,82.55 156.21,82.55 156.84,83.19 158.12,83.19 158.75,82.55 v167,82.55 | v167,111.76 IC39.26 178.44,111.76 179.71,113.03 195.58,113.03 196.85,111.76 IC38.26 | v165.74,24.13 v151.13,24.13 | v167.64,55.24 167.64,57.15 v168.28,57.15
EMA2  (via drill 0.61)
  Top 0.254: v90.17,80.64 90.81,81.28 90.81,87 89.53,88.27 89.53,89.53 IC19.12 | v24.77,62.23 26.67,60.33 26.67,40.64 17.78,31.75 17.78,15.24 v26.67,6.35 | v90.17,3.81 92.08,5.71 v92.08,8.26 | v104.78,8.26 109.22,12.7 v109.22,15.24 | v123.83,16.51 127,19.68 127,29.21 125.73,30.48 125.73,31.11 v126.36,31.75 | v192.41,114.3 191.77,113.67 191.77,64.77 191.13,64.14 v191.13,39.37 | v155.57,35.56 151.13,31.11 v151.13,29.21
  Bottom 0.254: IC39.2 172.72,114.3 173.99,113.03 178.44,113.03 179.07,113.67 182.25,113.67 IC38.2 v192.41,114.3 | v90.17,80.64 89.53,80.01 80.01,80.01 79.38,79.38 40.01,79.38 39.37,80.01 26.67,80.01 24.13,77.47 21.59,77.47 20.32,76.2 20.32,62.23 v24.77,62.23 | v26.67,6.35 27.3,5.71 64.14,5.71 66.67,3.17 87.63,3.17 88.9,4.45 89.53,4.45 v90.17,3.81 | v104.78,8.26 v92.08,8.26 | v109.22,15.24 110.49,16.51 v123.83,16.51 | v126.36,31.75 138.43,31.75 139.06,31.11 139.06,29.21 145.41,29.21 | 145.41,29.21 146.69,27.94 SV1.30 | v191.13,39.37 187.32,35.56 v155.57,35.56 | v151.13,29.21 145.41,29.21
ERROR  (via drill 0.61)
  Top 0.254: 141.6,67.94 144.78,71.12 v144.78,71.75 | 141.6,67.94 v140.34,66.67 | v150.5,73.03 149.86,73.66 149.86,106.68 IC9.19 | v50.8,81.28 50.8,110.49 51.44,111.12 51.44,130.18 IC10.6 | v81.92,81.92 83.82,81.92 v83.82,81.28 | v95.89,79.38 95.25,78.74 95.25,62.23 94.61,61.59 94.61,53.98 v93.98,53.34 | v142.88,53.34 141.6,54.61 141.6,67.94
  Bottom 0.254: v144.78,71.75 146.05,73.03 v150.5,73.03 | v140.34,66.67 IC6.19 | v50.8,81.28 51.44,81.92 63.5,81.92 64.77,80.64 78.11,80.64 79.38,81.92 v81.92,81.92 | v83.82,81.28 84.45,81.92 92.08,81.92 94.61,79.38 v95.89,79.38 | v93.98,53.34 95.25,52.07 118.11,52.07 120.65,49.53 141.6,49.53 142.88,50.8 v142.88,53.34
ERROR\
  Top 0.254: IC10.5 52.7,135.25 52.7,136.53 IC10.4 52.7,137.79 52.7,139.06 IC10.3
  Bottom 0.254: IC11.4 67.31,137.16 66.04,135.89 55.88,135.89 54.61,137.16 IC10.4
FLD0  (via drill 0.61)
  Top 0.254: v134.62,93.98 IC21.14 | 94.61,102.23 v95.25,101.6 | 94.61,102.23 92.71,104.14 IC19.17 | v97.16,90.17 95.25,90.17 95.25,97.16 94.61,97.79 94.61,102.23
  Bottom 0.254: v134.62,93.98 133.35,93.98 130.81,91.44 IC21.9 128.27,91.44 127.64,92.08 123.83,92.08 123.19,92.71 102.87,92.71 100.33,90.17 v97.16,90.17 | v95.25,101.6 RN3.2
FLD1  (via drill 0.61)
  Top 0.254: v133.99,101.6 133.35,100.97 133.35,96.52 132.08,95.25 130.18,95.25 130.18,95.89 IC21.7
  Bottom 0.254: IC19.14 97.79,96.52 100.33,99.06 RN3.3 102.87,99.06 104.14,97.79 123.19,97.79 124.46,96.52 IC21.7 | v133.99,101.6 IC21.16
FLD2  (via drill 0.61)
  Top 0.254: IC21.5 130.81,101.6 133.35,104.14 v133.35,106.68 133.99,107.31 133.99,120.65 v133.35,121.28 | v104.78,125.73 104.78,99.69 RN3.4 | v136.53,121.28 v136.53,125.09
  Bottom 0.254: IC19.13 92.71,93.98 93.98,95.25 99.06,95.25 100.33,96.52 RN3.4 | v133.35,106.68 IC21.18 | v104.78,125.73 116.84,125.73 117.47,126.36 118.75,125.09 132.72,125.09 133.35,124.46 135.89,124.46 v136.53,125.09 | v136.53,121.28 v133.35,121.28
GND  (via drill 0.61)
  Top 0.254: IC13.8 83.19,12.06 83.19,5.71 76.83,5.71 69.85,12.7 IC4.8 67.31,11.43 67.31,8.26 66.67,7.62 62.87,7.62 62.87,6.99 62.23,6.35 59.05,6.35 59.05,6.99 58.42,7.62 | IC47.10 116.2,9.53 116.2,10.79 IC47.8 | 112.39,45.09 112.39,46.35 IC46.8 | 112.39,45.09 IC46.10 | IC37.9 52.7,45.09 52.7,43.81 IC37.10 55.88,40.64 55.88,17.78 57.15,16.51 57.15,8.89 58.42,7.62 | v62.87,41.91 62.87,27.3 IC42.18 | IC27.9 67.94,45.09 67.94,43.81 IC27.10 | v126.36,37.47 126.36,36.83 127.64,36.83 128.91,38.1 128.27,38.73 128.27,41.91 IC6.10 | 112.39,45.09 108.58,41.27 v108.58,37.47 | v38.1,7.62 IC8.7 | IC2.12 33.66,17.14 33.66,5.08 37.47,1.27 52.07,1.27 52.07,7.62 IC42.10 | 9.53,130.81 9.53,132.72 IC7.5 | 9.53,130.81 9.53,128.91 IC7.8 | v19.68,133.35 17.14,130.81 9.53,130.81 | IC7.4 6.99,136.53 6.99,135.25 IC7.5 | IC7.5 5.08,132.08 5.08,99.06 IC31.7 6.35,95.25 6.35,60.33 7.62,59.05 QG2.7 7.62,57.78 9.53,55.88 9.53,17.14 IC12.7 | v57.78,7.62 58.42,7.62 | SV1.37 SV1.39 145.41,15.24 150.5,10.16 154.31,10.16 154.31,12.06 IC14.8 | IC18.7 198.75,14.61 198.75,23.5 IC18.2 198.75,27.3 198.75,46.35 IC20.7 | 116.2,90.81 116.2,92.08 IC48.8 | 116.2,90.81 IC48.10 | IC21.10 127.64,90.81 127.64,92.08 IC21.8 | 116.2,90.81 v118.11,90.81 | IC38.14 183.51,83.19 183.51,71.75 187.96,67.31 187.96,49.53 186.69,48.26 IC35.7 | IC9.10 v144.78,83.82 | IC30.10 67.94,89.53 67.94,90.81 IC30.9 67.94,92.08 67.94,93.34 IC30.8 67.94,94.61 67.94,95.89 IC30.7 67.94,97.16 67.94,98.42 IC30.6 67.94,99.69 67.94,100.97 IC30.5 67.94,102.23 67.94,103.5 IC30.4 | IC33.10 52.7,89.53 52.7,90.81 IC33.9 52.7,92.08 52.7,93.34 IC33.8 52.7,94.61 52.7,95.89 IC33.7 52.7,97.16 52.7,98.42 IC33.6 52.7,99.69 52.7,100.97 IC33.5 52.7,102.23 52.7,103.5 IC33.4 52.7,104.78 52.7,106.05 IC33.3 52.7,107.31 52.7,108.58 IC33.2 55.24,111.12 55.24,127.64 IC10.7
  Top 0.254: IC32.9 98.42,46.35 98.42,47.62 IC32.8 97.16,50.16 97.16,56.52 IC32.4 98.42,59.05 98.42,60.33 IC32.3 98.42,61.59 98.42,62.87 IC32.2 | IC5.1 85.09,67.31 85.09,88.9 IC19.10 | IC24.2 98.42,142.88 98.42,144.15 IC24.1 | IC28.2 83.19,142.88 83.19,144.15 IC28.1 | IC11.2 66.67,140.34 66.67,131.44 IC11.7 | IC19.1 83.19,112.39 83.19,126.36 IC28.8 | IC24.9 106.05,127.64 106.05,128.91 IC24.10 106.05,130.18 106.05,131.44 IC24.11 | v93.98,104.14 IC19.18 | IC28.9 90.81,127.64 90.81,128.91 IC28.10 90.81,130.18 90.81,131.44 IC28.11 | 99.06,106.68 RN3.1 | IC24.8 99.06,106.68 | IC34.13 151.76,137.79 151.76,139.06 IC34.14 151.76,140.34 151.76,141.6 IC34.15 | IC25.2 128.91,142.88 128.91,144.15 IC25.1 | IC41.8 159.38,127.64 159.38,128.91 IC41.7 | IC21.17 139.06,106.05 139.06,125.09 IC25.9 136.53,127.64 136.53,128.91 IC25.10 136.53,130.18 136.53,131.44 IC25.11 140.97,132.08 142.88,133.99 142.88,137.79 143.51,138.43 | v133.99,142.88 135.89,140.97 140.34,140.97 141.6,142.24 142.88,142.24 142.88,139.06 143.51,138.43 | v147.32,137.16 146.05,138.43 143.51,138.43 | v173.35,126.36 173.35,127.64 IC22.7 | v100.33,93.34 99.06,94.61 99.06,106.68
  Bottom 0.254: 101.6,13.97 102.23,13.34 113.67,13.34 IC47.8 | 101.6,13.97 100.33,15.24 IC17.7 | 101.6,13.97 86.36,13.97 85.09,12.7 IC13.8 | 81.92,42.55 81.28,41.91 71.12,41.91 69.85,43.18 IC27.10 64.14,43.18 v62.87,41.91 59.69,41.91 58.42,43.18 IC37.10 | 81.92,42.55 82.55,43.18 IC5.10 85.09,43.18 86.36,41.91 96.52,41.91 97.79,43.18 IC32.10 | v126.36,37.47 125.73,36.83 108.58,36.83 | 108.58,36.83 102.87,36.83 100.33,39.37 96.52,39.37 95.25,40.64 86.36,40.64 85.72,40.01 84.45,40.01 81.92,42.55 | 108.58,36.83 v108.58,37.47 | 38.1,8.26 52.7,8.26 IC42.10 v57.78,7.62 | 38.1,8.26 15.88,8.26 8.89,15.24 IC12.7 | 38.1,8.26 v38.1,7.62 | v19.68,133.35 27.94,133.35 29.21,134.62 IC3.12 | QG2.7 8.26,58.42 9.53,57.15 20.32,57.15 21.59,55.88 CPU.15 25.4,55.88 | 25.4,55.88 CPU.26 | 25.4,55.88 34.92,65.41 36.2,65.41 36.83,64.77 43.18,64.77 44.45,66.04 RN1.1 | IC1.12 138.43,20.32 140.97,17.78 SV1.37 | IC18.2 201.93,25.4 204.47,22.86 IC18.12 | 167.64,11.43 157.48,11.43 156.21,12.7 IC14.8 | 167.64,11.43 168.91,12.7 IC26.7 | 182.88,11.43 184.15,12.7 IC15.7 | 182.88,11.43 167.64,11.43 | 182.88,11.43 198.12,11.43 199.39,12.7 IC18.7 | 132.08,90.17 142.24,90.17 143.51,88.9 IC9.10 | 132.08,90.17 130.81,88.9 IC21.10 | v118.11,90.81 118.75,90.17 132.08,90.17 | IC38.14 181.61,83.82 180.34,85.09 173.99,85.09 172.72,83.82 IC39.14 v144.78,83.82 | IC29.7 156.21,48.26 158.12,46.35 166.37,46.35 168.28,48.26 IC36.7 171.45,48.26 172.72,49.53 182.88,49.53 | 182.88,49.53 184.15,48.26 IC35.7 | 182.88,49.53 198.12,49.53 199.39,48.26 IC20.7 | IC30.7 67.31,96.52 66.04,95.25 55.88,95.25 54.61,96.52 IC33.7 | IC32.2 97.79,63.5 96.52,64.77 87,64.77 85.72,66.04 IC5.1
  Bottom 0.254: IC30.10 69.85,88.9 71.12,87.63 81.28,87.63 82.55,88.9 IC19.10 | 50.8,128.27 40.64,128.27 39.37,129.54 IC40.7 36.83,129.54 32.38,125.09 24.13,125.09 23.5,124.46 11.43,124.46 8.89,127 IC7.8 | 50.8,128.27 52.07,129.54 IC10.7 | 50.8,128.27 66.04,128.27 67.31,129.54 IC11.7 69.85,129.54 71.12,128.27 80.64,128.27 81.92,127 IC28.8 IC28.9 IC24.8 IC24.9 | IC28.1 82.55,144.78 81.92,144.15 78.11,144.15 77.47,143.51 71.12,143.51 69.85,142.24 IC11.2 | IC24.1 97.79,144.78 97.16,144.15 93.34,144.15 92.71,143.51 90.17,143.51 88.9,142.24 IC28.2 | IC24.10 IC16.7 115.57,129.54 117.47,127.64 127,127.64 127.64,127 IC25.8 IC25.9 IC34.8 146.05,127 147.32,125.73 157.48,125.73 158.75,127 IC41.8 163.83,127 165.1,125.73 172.72,125.73 v173.35,126.36 | RN3.1 v93.98,104.14 | IC22.7 176.53,129.54 177.16,130.18 180.97,130.18 181.61,130.81 187.96,130.81 189.23,129.54 IC23.7 | v133.99,142.88 131.44,142.88 130.81,142.24 IC25.2 | v147.32,137.16 IC34.13 | v100.33,93.34 112.39,93.34 113.03,93.98 IC48.8
GTF\  (via drill 0.61)
  Top 0.254: v89.53,9.53 89.53,15.88 IC13.11 | v102.23,9.53 105.41,6.35 v105.41,3.17 | v147.32,2.54 v153.67,8.89 | v179.07,8.89 180.34,10.16 180.34,45.72 184.15,49.53 186.69,49.53 187.32,50.16 187.32,53.98 | 187.32,53.98 IC35.4 | v184.78,66.67 187.32,64.14 187.32,53.98 | v154.94,67.31 IC29.1
  Bottom 0.254: v89.53,9.53 99.06,9.53 99.69,8.89 101.6,8.89 v102.23,9.53 | v105.41,3.17 106.05,3.81 126.36,3.81 127.64,2.54 v147.32,2.54 | v153.67,8.89 v179.07,8.89 | v154.94,67.31 169.54,67.31 170.18,67.94 180.34,67.94 181.61,66.67 v184.78,66.67
HLT\  (via drill 0.61)
  Top 0.254: v73.03,29.21 74.3,27.94 74.3,24.77 IC4.13
  Bottom 0.254: v73.03,29.21 40.64,29.21 39.37,30.48 IC8.1
IFETCH  (via drill 0.61)
  Top 0.254: v56.52,80.64 56.52,145.41 59.05,147.96 62.87,147.96 | 62.87,147.96 62.87,141.6 IC10.12 | 172.72,147.96 v172.72,149.86 | 172.72,147.96 172.72,139.7 IC22.4 | v64.77,149.86 62.87,147.96 | v206.38,19.05 205.74,19.68 205.74,62.87 206.38,63.5 206.38,64.77 210.19,68.58 210.19,99.69 205.74,104.14 205.74,147.96 172.72,147.96
  Bottom 0.254: IC15.4 186.69,20.32 191.77,15.24 IC15.9 194.31,15.24 195.58,16.51 203.84,16.51 v206.38,19.05 | v56.52,80.64 55.88,80.01 40.64,80.01 39.37,81.28 CPU.36 | v172.72,149.86 171.45,151.13 66.04,151.13 v64.77,149.86
IFLD0  (via drill 0.61)
  Top 0.254: v71.12,16.51 71.12,48.26 IC27.7 71.12,53.34 v71.12,93.98 | v124.46,132.08 125.73,130.81 125.73,123.19 125.09,122.56 125.09,103.5 IC21.6 | v148.59,132.08 148.59,98.42 v147.96,97.79 | v98.42,92.71 97.79,93.34 97.79,113.03 v97.16,113.67 | v100.33,116.84 100.97,117.47 100.97,132.72 IC24.5
  Bottom 0.254: v71.12,16.51 67.31,16.51 66.04,15.24 IC42.14 | v124.46,132.08 123.19,133.35 104.14,133.35 102.87,134.62 IC24.5 | v147.96,97.79 132.08,97.79 130.81,99.06 IC21.6 | v148.59,132.08 IC34.11 | v71.12,93.98 72.39,95.25 86.36,95.25 88.9,92.71 v98.42,92.71 | v100.33,116.84 v97.16,113.67
IFLD1  (via drill 0.61)
  Top 0.254: v64.14,12.7 66.67,15.24 66.67,20.95 67.31,21.59 66.67,22.23 66.67,51.44 IC27.6 | v127.64,121.28 127.64,106.05 IC21.4 | v146.69,120.65 147.32,121.28 147.32,130.81 146.69,131.44 146.69,132.72 IC34.5 | v101.6,116.84 101.6,134.62 IC24.4 97.16,135.25 97.16,126.36 98.42,125.09 98.42,93.98 99.69,92.71 99.69,92.08 v99.06,91.44 | v116.2,115.57 116.84,116.2 v116.84,119.38 | v120.65,123.19 v120.65,119.38 | v74.3,52.07 74.3,61.59 74.93,62.23 78.11,62.23 v78.11,97.79 | v95.89,97.79 96.52,97.16 v96.52,91.44
  Bottom 0.254: v64.14,12.7 IC42.13 | v146.69,120.65 144.78,120.65 142.88,122.56 128.91,122.56 v127.64,121.28 125.09,121.28 123.83,122.56 121.28,122.56 v120.65,123.19 | v101.6,116.84 102.87,115.57 v116.2,115.57 | v120.65,119.38 v116.84,119.38 | v74.3,52.07 71.12,52.07 69.85,53.34 IC27.6 | v95.89,97.79 v78.11,97.79 | v99.06,91.44 v96.52,91.44
IFLD2  (via drill 0.61)
  Top 0.254: v33.66,40.01 33.66,27.94 34.29,27.3 34.29,5.71 37.47,5.71 41.91,10.16 41.91,16.51 46.99,16.51 47.62,15.88 47.62,12.7 IC42.8 | v73.03,40.01 v73.03,55.24 73.66,55.88 73.66,92.71 70.48,95.89 70.48,135.25 v73.66,138.43 | v126.36,109.22 126.36,133.99 127.64,135.25 v127.64,135.89 127.64,147.32 125.73,149.22 109.86,149.22 v109.86,142.24 | v133.99,135.89 v133.99,141.6
  Bottom 0.254: v33.66,40.01 34.29,39.37 72.39,39.37 v73.03,40.01 | v73.03,55.24 72.39,55.88 IC27.5 | v73.66,138.43 92.71,138.43 93.98,139.7 IC24.3 100.97,139.7 102.23,140.97 108.58,140.97 v109.86,142.24 | v126.36,109.22 IC21.2 | v133.99,141.6 135.89,143.51 138.43,143.51 139.06,142.88 142.88,142.88 143.51,142.24 IC34.2 | v127.64,135.89 v133.99,135.89
INHIBIT  (via drill 0.61)  (1 unrouted)
  Top 0.254: v71.75,109.22 73.66,111.12 73.66,124.46 79.38,130.18 79.38,136.53 81.28,138.43 v81.28,145.41 | v111.12,145.41 v111.12,142.24
  Bottom 0.254: v81.28,145.41 81.92,146.05 110.49,146.05 v111.12,145.41 | v71.75,109.22 IC30.2 | v111.12,142.24 IC16.2 | IC15.13 191.13,23.5 191.13,19.05 198.12,19.05 199.39,17.78 IC18.5
INTCLR  (via drill 0.61)
  Top 0.254: 102.23,136.53 102.87,135.89 103.5,135.89 103.5,136.53 104.78,137.79 104.78,140.34 IC24.15 | 102.23,136.53 101.6,137.16 101.6,146.05 96.52,146.05 92.71,142.24 IC28.15 | v149.86,123.19 149.86,132.08 151.13,133.35 150.5,133.99 v150.5,143.51 150.5,146.05 142.24,146.05 138.43,142.24 IC25.15 | v124.46,123.19 123.83,122.56 v123.83,114.3 | v103.5,113.03 102.87,113.67 102.87,132.08 102.23,132.72 102.23,136.53 | v186.69,139.7 186.69,130.81 190.5,127 190.5,90.81 189.87,90.17 189.87,48.9 181.61,40.64 181.61,10.16 182.25,9.53 182.25,7.62 179.07,7.62 171.45,15.24 IC26.6
  Bottom 0.254: v149.86,123.19 v124.46,123.19 | v123.83,114.3 123.19,113.67 110.49,113.67 109.86,113.03 v103.5,113.03 | v186.69,139.7 185.42,140.97 156.21,140.97 153.67,143.51 v150.5,143.51
INTCLR\  (1 unrouted)
  Top 0.254: IC26.4 169.54,20.95 169.54,22.23 IC26.3
INTGNT  (via drill 0.61)
  Top 0.254: v169.54,40.64 169.54,28.57 IC26.1 172.09,26.04 v172.09,16.51 | v151.13,41.91 150.5,42.55 150.5,53.98 149.86,54.61 149.86,57.78 v150.5,58.42 | v56.52,41.27 56.52,18.41 57.78,17.14 57.78,9.53 59.69,7.62 IC42.11 | v48.9,41.27 49.53,41.91 49.53,61.59 47.62,63.5 47.62,70.48 46.35,71.75 v46.35,87.63 | v142.24,12.7 136.53,6.99 136.53,4.45 133.99,1.91 116.2,1.91 v110.49,7.62
  Bottom 0.254: v169.54,40.64 168.28,41.91 v151.13,41.91 | v150.5,58.42 SV1.6 | v56.52,41.27 v48.9,41.27 | v46.35,87.63 45.09,88.9 CPU.39 | v172.09,16.51 172.09,13.97 150.5,13.97 149.22,12.7 v142.24,12.7 | v110.49,7.62 109.86,6.99 83.19,6.99 81.92,8.26 61.59,8.26 IC42.11
IO_RESET\
  Bottom 0.254: IC29.10 161.29,53.34 160.02,52.07 146.69,52.07 145.41,50.8 SV1.11
IOT\
  Top 0.254: IC7.9 9.53,127 9.53,108.58 IC31.3
  Bottom 0.254: IC8.5 36.83,20.32 35.56,21.59 6.35,21.59 2.54,25.4 2.54,106.68 IC31.3
IR0
  Bottom 0.254: IC7.3 12.7,134.62 12.7,125.73 27.94,125.73 29.21,127 IC3.9
IR1
  Bottom 0.254: IC7.2 13.34,136.53 13.34,130.81 27.94,130.81 29.21,129.54 IC3.10
IR2
  Bottom 0.254: IC7.1 8.89,144.78 10.16,143.51 16.51,143.51 17.14,144.15 20.95,144.15 21.59,143.51 27.94,143.51 29.21,142.24 IC3.15
IR3  (via drill 0.61)
  Top 0.254: v41.91,19.05 41.91,34.92 v40.64,36.2 | v32.38,37.47 29.84,40.01 29.84,118.11 32.38,120.65 32.38,142.88 IC3.16
  Bottom 0.254: v41.91,19.05 66.04,19.05 67.31,17.78 IC4.6 | v40.64,36.2 33.66,36.2 v32.38,37.47
IR3\  (via drill 0.61)
  Top 0.254: v4.45,27.94 4.45,147.32 16.51,147.32 19.05,144.78 IC3.1
  Bottom 0.254: 17.78,26.67 16.51,25.4 IC12.12 | 17.78,26.67 43.18,26.67 44.45,27.94 IC8.13 | v4.45,27.94 5.71,26.67 17.78,26.67
IR4  (via drill 0.61)
  Top 0.254: v40.64,12.7 v40.64,25.4
  Bottom 0.254: IC2.9 v40.64,12.7 | v40.64,25.4 IC8.12
IR4\  (via drill 0.61)
  Top 0.254: v19.05,22.86 19.05,16.51 IC2.8
  Bottom 0.254: v19.05,22.86 IC12.11
IR5\
  Bottom 0.254: 27.94,19.05 10.16,19.05 8.89,17.78 IC12.6 | 27.94,19.05 29.21,17.78 IC2.11 | 27.94,19.05 39.37,19.05 40.64,20.32 IC8.10
IR6  (via drill 0.61)
  Top 0.254: v34.92,27.94 35.56,27.3 v35.56,6.99 | v73.03,4.45 75.56,1.91 97.16,1.91 v97.16,16.51 | v125.73,24.13 124.46,22.86 124.46,20.32 IC47.15
  Bottom 0.254: IC47.15 IC47.6 110.49,17.78 109.22,16.51 105.41,16.51 104.14,15.24 103.5,15.24 102.87,15.88 102.23,15.88 101.6,16.51 v97.16,16.51 | v35.56,6.99 36.2,6.35 70.48,6.35 72.39,4.45 v73.03,4.45 | v34.92,27.94 IC2.15 | v125.73,24.13 147.96,24.13 149.22,25.4 IC14.3
IR6\  (via drill 0.61)
  Top 0.254: v12.7,20.32 v12.7,22.86
  Bottom 0.254: v12.7,22.86 13.97,24.13 27.94,24.13 29.21,25.4 IC2.14 | IC12.5 v12.7,20.32
IR7  (via drill 0.61)
  Top 0.254: 116.84,13.97 116.84,20.32 IC47.4 | 116.84,13.97 116.84,8.89 118.11,8.89 IC47.13 | v33.02,25.4 33.02,27.94 IC2.16 | v109.86,26.67 109.86,17.14 113.03,13.97 116.84,13.97 | v151.76,27.94 152.4,27.3 152.4,17.14 v149.22,13.97
  Bottom 0.254: v33.02,25.4 34.29,24.13 102.87,24.13 105.41,26.67 v109.86,26.67 | v149.22,13.97 148.59,13.34 142.88,13.34 142.24,13.97 127,13.97 125.73,12.7 IC47.13 | v151.76,27.94 IC14.2
IR7\
  Bottom 0.254: IC12.4 3.17,27.3 3.17,29.21 20.32,29.21 21.59,30.48 IC2.1
IR8  (via drill 0.61)
  Top 0.254: v136.53,10.16 136.53,12.06 IC1.9 | v109.86,27.94 108.58,26.67 108.58,17.14 110.49,15.24 v110.49,8.89 | v153.03,11.43 153.03,28.57 IC14.1
  Bottom 0.254: 124.46,8.89 125.73,10.16 v136.53,10.16 | 124.46,8.89 123.19,7.62 IC47.11 | v110.49,8.89 124.46,8.89 | v109.86,27.94 IC47.2 | v153.03,11.43 140.97,11.43 139.7,12.7 IC1.9
IR8\  (via drill 0.61)
  Top 0.254: v5.71,3.81 5.71,23.5 IC12.3 | v56.52,3.81 60.96,3.81 62.23,5.08 72.39,5.08 v72.39,5.71 | v131.44,5.71 130.18,6.99 130.18,12.06 IC1.8
  Bottom 0.254: v5.71,3.81 v56.52,3.81 | v72.39,5.71 v131.44,5.71
IR9  (via drill 0.61)
  Top 0.254: v149.22,15.24 151.13,17.14 v151.13,17.78 | v131.44,8.89 131.44,9.53 IC1.10 | v81.92,6.99 81.92,23.5 IC13.3
  Bottom 0.254: v149.22,15.24 147.96,13.97 144.15,13.97 143.51,14.61 139.06,14.61 138.43,15.24 IC1.10 | v151.13,17.78 IC14.6 | 81.28,26.67 74.93,26.67 73.66,25.4 IC4.3 | 81.28,26.67 82.55,25.4 IC13.3 | 81.28,26.67 92.71,26.67 93.98,27.94 IC17.2 | v131.44,8.89 128.91,6.35 82.55,6.35 v81.92,6.99
IR10
  Bottom 0.254: IC4.2 73.66,27.94 74.93,29.21 80.64,29.21 81.92,27.94 IC13.2 85.72,27.94 87,29.21 134.62,29.21 135.89,27.94 IC1.15
IR10\  (via drill 0.61)
  Top 0.254: v132.08,19.05 132.72,19.68 v132.72,25.4
  Bottom 0.254: v132.08,19.05 101.6,19.05 100.33,20.32 IC17.5 | v132.72,25.4 IC1.14
IR11  (via drill 0.61)
  Top 0.254: v73.03,30.48 74.93,32.38 74.93,40.64 76.2,41.91 78.74,41.91 78.74,39.37 83.19,34.92 83.19,31.11 IC13.1 85.72,28.57 85.72,9.53 v87,8.26 | v132.72,30.48 132.08,29.84 132.08,26.04 131.44,25.4 131.44,19.68 130.81,19.05 127.64,19.05 v127.64,3.81 | v95.89,3.81 93.34,6.35 93.34,8.26 92.08,9.53 90.81,9.53 v90.81,8.26
  Bottom 0.254: v73.03,30.48 IC4.1 | v127.64,3.81 127,4.45 96.52,4.45 v95.89,3.81 | v87,8.26 v90.81,8.26 | v132.72,30.48 IC1.16
IR11\  (via drill 0.61)
  Top 0.254: v111.76,20.32 111.76,40.01 v111.12,40.64 | v129.54,39.37 IC1.1
  Bottom 0.254: v111.12,40.64 128.27,40.64 v129.54,39.37 | IC17.10 v111.76,20.32
ISZ\
  Top 0.254: IC7.13 PAD3.1
JMP\
  Bottom 0.254: IC7.10 16.51,129.54 17.78,128.27 34.29,128.27 36.83,130.81 49.53,130.81 52.07,133.35 58.42,133.35 59.69,132.08 IC10.9
JMP_OR_JMS  (1 unrouted)
JMPDONE  (via drill 0.61)  (1 unrouted)
  Top 0.254: v23.5,123.19 23.5,112.39 IC31.11 | v95.89,124.46 v95.89,129.54 | IC15.8 191.13,14.61 191.13,20.95 IC15.12
  Bottom 0.254: v23.5,123.19 24.77,124.46 38.1,124.46 38.73,125.09 73.66,125.09 74.3,124.46 v95.89,124.46 | v95.89,129.54 IC24.7 | IC15.12 IC18.3
JMS\  (via drill 0.61)
  Top 0.254: v13.34,146.05 13.34,133.99 IC7.11 | v59.05,146.69 59.05,136.53 IC10.10
  Bottom 0.254: v13.34,146.05 13.97,146.69 v59.05,146.69
LINK
  Top 0.254: PAD5.1 CPU.29
LXMAR  (via drill 0.61)
  Top 0.254: v168.28,29.21 168.28,27.3 IC26.2 | IC19.11 91.44,79.38 89.53,77.47 v89.53,70.48 89.53,45.09 IC5.11 92.08,42.55 92.08,33.02 v93.98,31.11
  Bottom 0.254: v168.28,29.21 152.4,29.21 151.13,30.48 SV1.28 146.69,30.48 145.41,31.75 139.7,31.75 139.06,32.38 127,32.38 126.36,33.02 120.02,33.02 118.11,31.11 117.47,31.11 116.84,31.75 94.61,31.75 v93.98,31.11 | v89.53,70.48 88.27,70.48 86.36,68.58 53.34,68.58 49.53,72.39 20.95,72.39 20.95,70.48 CPU.10
MA0  (via drill 0.61)
  Top 0.254: v87.63,12.7 87.63,27.94 85.72,29.84 85.72,33.66 79.38,40.01 79.38,53.34 80.01,53.98 80.01,59.69 78.74,60.96 78.74,86.36 IC19.9 | v111.76,10.16 112.39,9.53 112.39,6.99 116.84,2.54 133.35,2.54 v133.35,5.08
  Bottom 0.254: v87.63,12.7 88.9,11.43 99.69,11.43 100.97,12.7 106.68,12.7 109.22,10.16 v111.76,10.16 | v133.35,5.08 213.36,5.08 214,5.71 214,103.5 198.75,103.5 IC38.23 196.85,104.14 195.58,105.41 177.8,105.41 176.53,104.14 IC39.23
MA1
  Bottom 0.254: IC19.6 85.09,99.06 85.72,99.69 89.53,99.69 90.17,100.33 161.93,100.33 163.19,99.06 IC39.21 175.9,99.69 180.97,99.69 181.61,100.33 195.58,100.33 196.85,99.06 IC38.21
MA2  (via drill 0.61)
  Top 0.254: v80.64,115.57 v80.64,101.6 | v90.81,115.57 92.08,116.84 92.08,125.09 93.34,126.36 93.34,138.43 v95.89,140.97 | v104.14,142.24 105.41,143.51 104.78,144.15 v104.78,147.96
  Bottom 0.254: v90.81,115.57 v80.64,115.57 | v95.89,140.97 100.97,140.97 102.23,142.24 v104.14,142.24 | v104.78,147.96 105.41,148.59 131.44,148.59 132.72,147.32 164.47,147.32 165.1,147.96 198.75,147.96 212.09,134.62 212.09,107.31 198.75,107.31 IC38.24 196.85,106.68 195.58,107.95 181.61,107.95 180.97,107.31 177.16,107.31 176.53,106.68 IC39.24 | v80.64,101.6 IC19.5
MA3  (via drill 0.61)
  Top 0.254: v87,109.22 87,97.16 87.63,96.52 87.63,90.17 v87,89.53 | v108.58,91.44 109.22,92.08 v109.22,94.61 | v116.84,96.52 119.38,99.06 119.38,115.57 118.11,116.84 118.11,124.46 119.38,125.73 119.38,134.62 120.65,135.89 123.83,135.89 v123.83,146.69 | v165.1,146.69 163.83,147.96 163.83,149.86 165.1,151.13 171.45,151.13 171.45,144.78 172.09,144.15 172.09,112.39 IC39.25
  Bottom 0.254: v87,89.53 88.9,87.63 104.78,87.63 v108.58,91.44 | v109.22,94.61 109.86,95.25 115.57,95.25 v116.84,96.52 | v123.83,146.69 v165.1,146.69 | v87,109.22 IC19.2 | IC38.25 196.85,109.22 195.58,110.49 181.61,110.49 180.34,109.22 IC39.25
MA4  (via drill 0.61)
  Top 0.254: v93.34,81.92 93.34,65.41 IC5.19 | v157.48,80.64 158.12,81.28 158.12,81.92 157.48,82.55 157.48,97.16 158.12,97.79 158.12,109.86 IC39.3
  Bottom 0.254: v93.34,81.92 94.61,83.19 116.84,83.19 118.75,81.28 156.21,81.28 156.84,80.64 v157.48,80.64 | IC38.3 181.61,111.76 180.34,110.49 162.56,110.49 161.29,111.76 IC39.3
MA5  (via drill 0.61)
  Top 0.254: v94.61,80.64 93.98,80.01 93.98,64.77 93.34,64.14 93.34,57.78 IC5.16 | v130.18,79.38 131.44,80.64 v131.44,85.72 | v167.64,87.63 167.64,106.05 v168.28,106.68
  Bottom 0.254: v94.61,80.64 95.89,81.92 115.57,81.92 118.11,79.38 v130.18,79.38 | v131.44,85.72 156.84,85.72 158.75,87.63 v167.64,87.63 | 167,107.95 165.74,109.22 IC39.4 | v168.28,106.68 167,107.95 | 167,107.95 180.34,107.95 181.61,109.22 IC38.4
MA6  (via drill 0.61)
  Top 0.254: v95.89,80.64 94.61,79.38 94.61,64.14 93.98,63.5 93.98,55.88 IC5.15 | v114.94,80.64 119.38,76.2 v119.38,69.85 | v135.89,69.85 135.89,70.48 v139.06,73.66 | v181.61,73.66 180.34,74.93 180.34,96.52 180.97,97.16 180.97,104.78 IC38.5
